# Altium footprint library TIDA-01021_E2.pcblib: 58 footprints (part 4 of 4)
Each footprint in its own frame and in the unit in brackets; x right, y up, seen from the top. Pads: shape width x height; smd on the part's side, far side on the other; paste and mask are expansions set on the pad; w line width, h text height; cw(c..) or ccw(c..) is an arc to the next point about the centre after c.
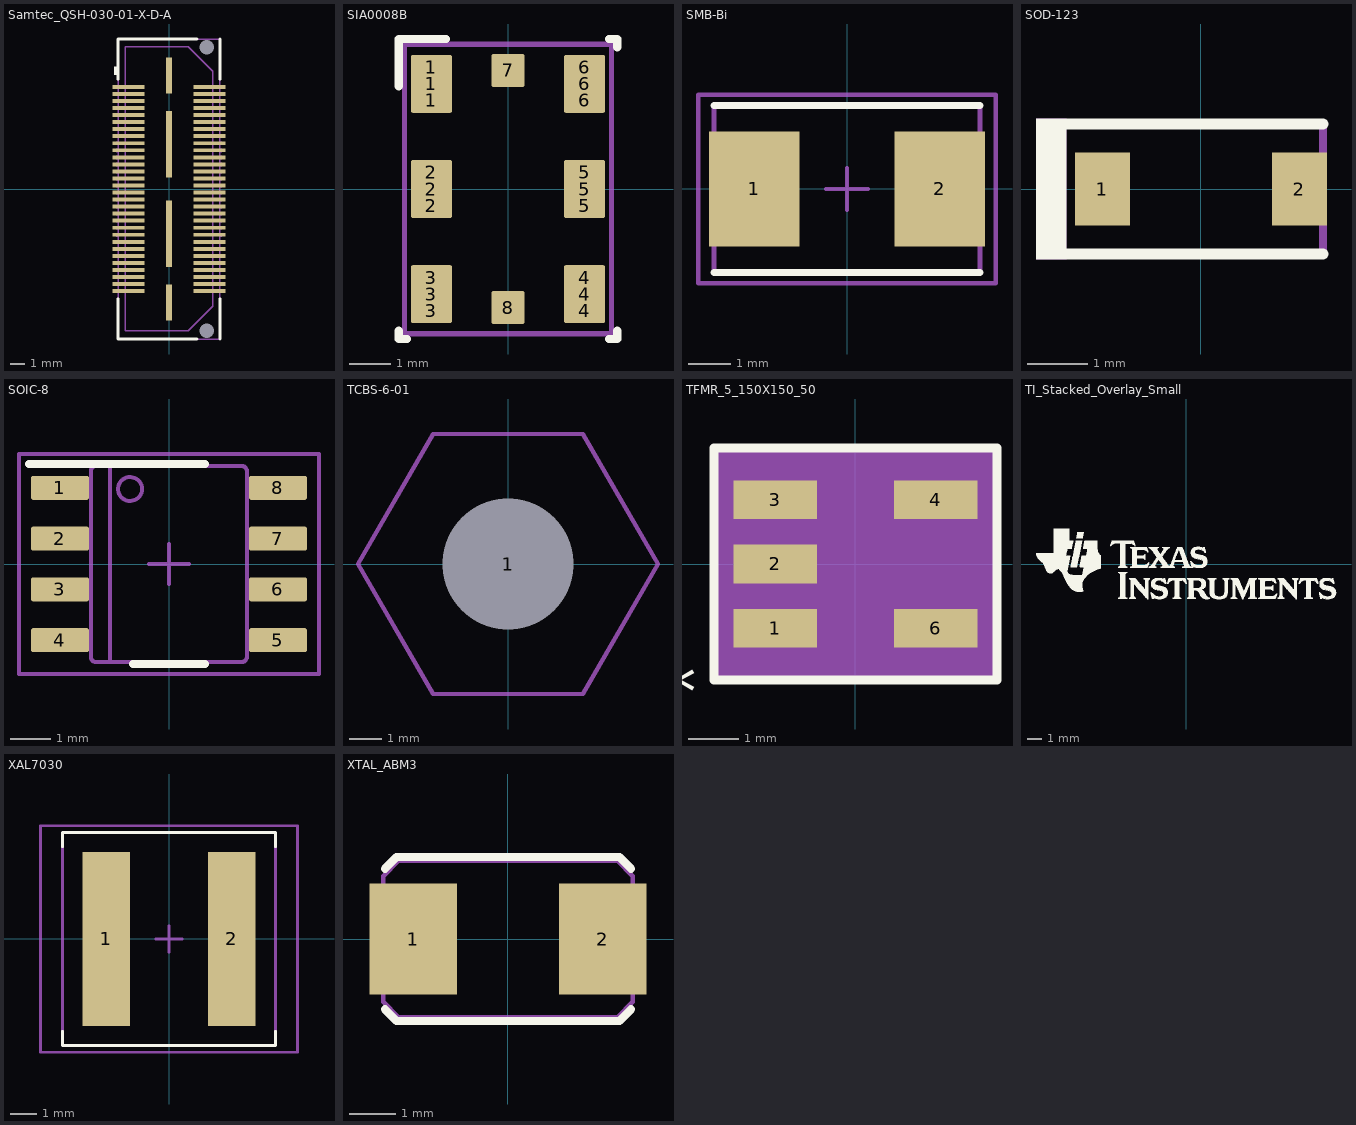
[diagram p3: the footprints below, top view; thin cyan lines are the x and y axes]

## Samtec_QSH-030-01-X-D-A [mm] "Receptacle, 0.5 mm, 30x2, TH"
height 3.327
pads (66):
  rect 2.27x0.279 smd: 1(-2.865,7.25) 2(2.865,7.25) 3(-2.865,6.75) 4(2.865,6.75) 5(-2.865,6.25) 6(2.865,6.25) 7(-2.865,5.75) 8(2.865,5.75) 9(-2.865,5.25) 10(2.865,5.25) 11(-2.865,4.75) 12(2.865,4.75) 13(-2.865,4.25) 14(2.865,4.25) 15(-2.865,3.75) 16(2.865,3.75) 17(-2.865,3.25) 18(2.865,3.25) 19(-2.865,2.75) 20(2.865,2.75) 21(-2.865,2.25) 22(2.865,2.25) 23(-2.865,1.75) 24(2.865,1.75) 25(-2.865,1.25) 26(2.865,1.25) 27(-2.865,0.75) 28(2.865,0.75) 29(-2.865,0.25) 30(2.865,0.25) 31(-2.865,-0.25) 32(2.865,-0.25) 33(-2.865,-0.75) 34(2.865,-0.75) 35(-2.865,-1.25) 36(2.865,-1.25) 37(-2.865,-1.75) 38(2.865,-1.75) 39(-2.865,-2.25) 40(2.865,-2.25) 41(-2.865,-2.75) 42(2.865,-2.75) 43(-2.865,-3.25) 44(2.865,-3.25) 45(-2.865,-3.75) 46(2.865,-3.75) 47(-2.865,-4.25) 48(2.865,-4.25) 49(-2.865,-4.75) 50(2.865,-4.75) 51(-2.865,-5.25) 52(2.865,-5.25) 53(-2.865,-5.75) 54(2.865,-5.75) 55(-2.865,-6.25) 56(2.865,-6.25) 57(-2.865,-6.75) 58(2.865,-6.75) 59(-2.865,-7.25) 60(2.865,-7.25)
  round 0 hole 1.02 unplated: MH1(2.67,10.065) MH2(2.67,-10.065)
  rect 0.43x2.54 smd: MP1(0,8.065) MP4(0,-8.065)
  rect 0.43x4.7 smd: MP2(0,3.175) MP3(0,-3.175)
Top Overlay:
  rectangle: -3.9,8.1 -3.62,8.7
  lines w0.2: -3.62,-7.789 -3.62,-10.655 2,-10.655 ; -3.62,7.789 -3.62,10.655 2,10.655 ; 3.62,-10.655 3.62,-7.789 ; 3.62,7.789 3.62,10.655
Mechanical 5:
  drawing of 190 lines, arcs and shapes, not listed
  text ".Designator" at -0.725,-0.543 h0.64
3D body "Samtec-QSH-030-01-L-D-A.stp": height 3.25, standoff -0.75, extent -3.746,-10.636 3.747,10.674

## SIA0008B [mm] "SIP 8-Leads, Body 5x7mm"
height 1.1
pads (20):
  rrect50% 1x0.6 on Top Paste: 1(-1.85,2.14) 1(-1.85,2.94) 2(-1.85,-0.4) 2(-1.85,0.4) 3(-1.85,-2.94) 3(-1.85,-2.14) 4(1.85,-2.94) 4(1.85,-2.14) 5(1.85,-0.4) 5(1.85,0.4) 6(1.85,2.14) 6(1.85,2.94)
  rrect10% 1x1.4 smd paste-0.5: 1(-1.85,2.54) 2(-1.85,0) 3(-1.85,-2.54) 4(1.85,-2.54) 5(1.85,0) 6(1.85,2.54)
  rrect12% 0.8x0.8 smd: 7(0,2.865) 8(0,-2.865)
Top Overlay:
  lines w0.2: -2.64,-3.425 -2.64,-3.625 -2.44,-3.625 ; -2.64,2.485 -2.64,3.625 -1.5,3.625 ; 2.44,-3.625 2.64,-3.625 2.64,-3.425 ; 2.44,3.625 2.64,3.625 2.64,3.425
Mechanical 5:
  circle w0.1: c-1.84,2.54 r0.25
  lines w0.127: -2.5,-3.5 2.5,-3.5 2.5,3.5 -2.5,3.5 -2.5,-3.5
  text ".Designator" at 0.511,0.186 h0.64
3D body: height 1.1, standoff 0, extent -2.564,-3.564 2.564,3.564
3D body: height 1.13, standoff 0, extent -2.156,2.224 -1.525,2.856

## SMB-Bi [mm] "Molded Diode, 2-Leads, Body 5.4x3.6mm, IPC Medium Density, based on OnSemi component dimensions"
height 2.65
pads (2):
  rect 2.159x2.743 smd: 1(-2.21,0) 2(2.21,0)
Top Overlay:
  lines w0.178: -3.175,-1.994 3.175,-1.994 ; -3.175,1.994 3.175,1.994
Mechanical 5:
  lines w0.127: -3.175,-1.994 3.175,-1.994 3.175,-1.765 3.175,1.765 3.175,1.994 -3.175,1.994 -3.175,1.765 -3.175,-1.765 -3.175,-1.994
  text ".Designator" at 0.249,-0.504 h0.64
Mechanical 15:
  lines w0.1: -0.5,0 0.5,0 ; 0,-0.5 0,0.5 ; -3.55,-2.25 -3.55,2.25 3.55,2.25 3.55,-2.25 -3.55,-2.25
3D body "SMB-Bi.stp": height 2.26, standoff 0.01, extent -2.65,-1.85 2.65,1.85

## SOD-123 [mm] "On Semi recommended land pattern"
height 1.35
pads (2):
  rect 0.915x1.22 smd: 1(-1.637,0) 2(1.637,0)
Top Overlay:
  rectangle: -2.742,-1.168 -2.234,1.168
  lines w0.178: -2.413,-1.079 2.032,-1.079 ; -2.413,1.079 2.032,1.079
Mechanical 5:
  rectangle: -2.742,-1.168 -2.234,1.168
  lines w0.127: -2.413,-1.079 2.032,-1.079 2.032,1.079 -2.413,1.079
  text ".Designator" at -0.722,0.389 h0.64
3D body "SOD-123.stp": height 1.35, standoff 0, extent -1.932,-0.9 1.932,0.9

## SOIC-8 [mm] "duplicate of SO-8.  SOIC, 8-Leads, Body 5.0x4.0mm (max), Pitch 1.27mm, IPC Medium Density"
height 1.75
pads (8):
  rrect17% 1.45x0.6 smd: 1(-2.725,1.905) 2(-2.725,0.635) 3(-2.725,-0.635) 4(-2.725,-1.905) 5(2.725,-1.905) 6(2.725,-0.635) 7(2.725,0.635) 8(2.725,1.905)
Top Overlay:
  lines w0.2: -3.5,2.5 0.9,2.5 ; -0.9,-2.5 0.9,-2.5
Mechanical 5:
  circle w0.1: c-0.975,1.875 r0.3
  lines w0.1: -1.475,-2.45 -1.475,2.45 ; -2.375,-2.095 -1.995,-2.095 -1.952,-2.095 -1.952,-1.715 -1.995,-1.715 -2.375,-1.715 ; -2.375,-2.095 -2.589,-2.095 -3.002,-2.095 -3.002,-1.715 -2.589,-1.715 -2.375,-1.715 ; -2.375,-2.095 -2.375,-1.715 ; -2.375,-0.825 -1.995,-0.825 -1.952,-0.825 -1.952,-0.445 -1.995,-0.445 -2.375,-0.445 ; -2.375,-0.825 -2.589,-0.825 -3.002,-0.825 -3.002,-0.445 -2.589,-0.445 -2.375,-0.445 ; -2.375,-0.825 -2.375,-0.445 ; -2.375,0.445 -1.995,0.445 -1.952,0.445 -1.952,0.825 -1.995,0.825 -2.375,0.825 ; -2.375,0.445 -2.589,0.445 -3.002,0.445 -3.002,0.825 -2.589,0.825 -2.375,0.825 ; -2.375,0.445 -2.375,0.825 ; -2.375,1.715 -1.995,1.715 -1.952,1.715 -1.952,2.095 -1.995,2.095 -2.375,2.095 ; -2.375,1.715 -2.589,1.715 -3.002,1.715 -3.002,2.095 -2.589,2.095 -2.375,2.095 ; -2.375,1.715 -2.375,2.095 ; -0.332,-2.45 -1.825,-2.45 -1.826,-2.45 cw(c-1.825,-2.323) -1.952,-2.324 -1.952,-2.323 -1.952,2.323 -1.952,2.324 cw(c-1.825,2.323) -1.826,2.45 -1.825,2.45 -0.332,2.45 ; -0.332,-2.45 -0.182,-2.45 ; -0.332,-2.45 -0.182,-2.45 ; -0.332,2.45 -0.182,2.45 ; -0.332,2.45 -0.182,2.45 ; -0.182,-2.45 0.178,-2.45 ; -0.182,2.45 0.178,2.45 ; 0.178,-2.45 0.328,-2.45 ; 0.178,-2.45 0.328,-2.45 ; 0.178,2.45 0.328,2.45 ; 0.178,2.45 0.328,2.45 ; 0.328,-2.45 1.821,-2.45 1.822,-2.45 ccw(c1.821,-2.323) 1.948,-2.324 1.948,-2.323 1.948,2.323 1.948,2.324 ccw(c1.821,2.323) 1.822,2.45 1.821,2.45 0.328,2.45 ; 2.371,-2.095 2.585,-2.095 2.998,-2.095 2.998,-1.715 2.585,-1.715 2.371,-1.715 ; 2.371,-2.095 1.991,-2.095 1.948,-2.095 1.948,-1.715 1.991,-1.715 2.371,-1.715 ; 2.371,-2.095 2.371,-1.715 ; 2.371,-0.825 2.585,-0.825 2.998,-0.825 2.998,-0.445 2.585,-0.445 2.371,-0.445 ; 2.371,-0.825 1.991,-0.825 1.948,-0.825 1.948,-0.445 1.991,-0.445 2.371,-0.445 ; 2.371,-0.825 2.371,-0.445 ; 2.371,0.445 2.585,0.445 2.998,0.445 2.998,0.825 2.585,0.825 2.371,0.825 ; 2.371,0.445 1.991,0.445 1.948,0.445 1.948,0.825 1.991,0.825 2.371,0.825 ; 2.371,0.445 2.371,0.825 ; 2.371,1.715 2.585,1.715 2.998,1.715 2.998,2.095 2.585,2.095 2.371,2.095 ; 2.371,1.715 1.991,1.715 1.948,1.715 1.948,2.095 1.991,2.095 2.371,2.095 ; 2.371,1.715 2.371,2.095
  text ".Designator" at 0.478,0.14 h0.64
Mechanical 15:
  lines w0.1: -0.5,0 0.5,0 ; 0,-0.5 0,0.5 ; -3.75,-2.75 3.75,-2.75 3.75,2.75 -3.75,2.75 -3.75,-2.75
3D body "SOIC-8akaD0008AakaM08A.stp": height 1.63, standoff 0, extent -3,-2.45 3,2.45

## TCBS-6-01 [mil] "Richco Plastics"
height 375
pads (1):
  round 60 hole 157 unplated: 1(0,0)
Mechanical 5:
  lines w5: -179.57,0 -89.79,155.51 89.78,155.51 179.56,0 89.78,-155.51 -89.79,-155.51 -179.57,0
  text ".Designator" at -60,-20 h25
3D body "Richco_TCBS-6.stp": height 374.61, standoff -387.62, extent -179.57,-155.51 179.56,155.51

## TFMR_5_150X150_50 [mil] "TFMR_5_150X150_50"
pads (5):
  rect 65x30 smd: 1(-62.5,-50) 2(-62.5,0) 3(-62.5,50) 4(62.5,50) 6(62.5,-50)
Top Overlay:
  lines w7: -110,-90 110,-90 110,90 -110,90 -110,-90
  text ".Designator" at -72.4,-158.33 h37
  text "*" at -123.2,-61 h42
Mechanical 5:
  lines w1: -75,-75 75,-75 75,75 -75,75 -75,-75
  text "*" at -80,-48.33 h25
Mechanical 16:
  region: 110,-90 -110,-90 -110,90 110,90
Mechanical 27:
  text "2" at -52.5,0 h25
  text "4" at 72.5,50 h25
  text "6" at 72.5,-50 h25
  text "1" at -52.5,-50 h25
  text "3" at -52.5,50 h25

## TI_Stacked_Overlay_Small [mm]
height 9.53
Top Overlay:
  drawing of 18 lines, arcs and shapes, not listed

## XAL7030 [mm] "Coilcraft XAL7030 7.5 x.7.5 x 3.1 mm"
height 3.1
pads (2):
  rect 1.78x6.55 smd: 1(-2.36,0) 2(2.36,0)
Top Overlay:
  lines w0.1: -4,-3.46 -4,-4 4,-4 4,-3.46 ; -4,3.46 -4,4 4,4 4,3.46
Mechanical 5:
  lines w0.1: -4,-4 4,-4 4,4 -4,4 -4,-4
  text ".Designator" at 0.229,-0.914 h0.64
Mechanical 15:
  lines w0.1: -0.5,0 0.5,0 ; 0,-0.5 0,0.5 ; -4.825,-4.25 4.825,-4.25 4.825,4.25 -4.825,4.25 -4.825,-4.25
3D body: height 3.1, standoff 0, extent -4,-4 4,4

## XTAL_ABM3 [mm] "Abracon recommended land pattern 12.28.10"
height 1.3
pads (2):
  rect 1.9x2.4 smd: 1(-2.05,0) 2(2.05,0)
Top Overlay:
  lines w0.178: -2.667,-1.524 -2.413,-1.778 0,-1.778 2.413,-1.778 2.667,-1.524 ; -2.667,1.524 -2.413,1.778 0,1.778 2.413,1.778 2.667,1.524
Mechanical 5:
  lines w0.1: -2.7,-1.364 -2.364,-1.7 2.364,-1.7 2.7,-1.364 2.7,1.364 2.364,1.7 -2.364,1.7 -2.7,1.364 -2.7,-1.364
  text ".Designator" at -0.287,0.566 h0.64
3D body "Abracon_ABM3.stp": height 1.3, standoff 0, extent -2.597,-1.698 2.603,1.702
